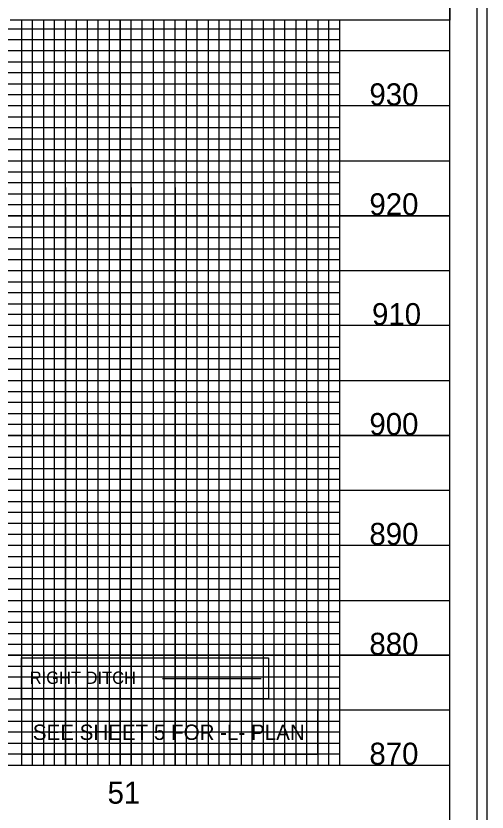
# Model space of a CAD drawing. Extents: x 1648649 to 1651827, y 844691 to 845879.
# Drawn here: x 1651431.8 to 1651646.3, y 845244.7 to 845606.9 of the extents above; entities that cross this region are included whole.
import ezdxf

# ---------------------------------------------------------------- set-up
doc = ezdxf.new("R2010")
doc.units = 0
for name, color, linetype in [('Exist Vertical Profile Horizontal Axis Label Major', 7, 'Continuous'), ('Exist Vertical Profile Vertical Axis Label', 7, 'Continuous'), ('Prop Dimension', 7, 'Continuous'), ('Prop Grid Mask', 7, 'Continuous'), ('Prop PFL Ditch Label CELL', 7, 'Continuous'), ('Sheet DOT Grid CELL', 7, 'Continuous'), ('Sheet Plot Border Inside CELL', 7, 'Continuous'), ('Sheet Plot Border Outside CELL', 7, 'Continuous'), ('Sheet Profile CELL', 7, 'Continuous'), ('Sheet Profile Grid Major CELL', 7, 'Continuous'), ('Sheet Profile Grid Middle CELL', 7, 'Continuous'), ('Sheet Profile Grid Minor CELL', 7, 'Continuous'), ('Sheet Sticker Exception Certification CELL', 7, 'Continuous')]:
    doc.layers.add(name, color=color, linetype=linetype)

msp = doc.modelspace()

# ---------------------------------------------------------------- linework, layer by layer
at = {"layer": 'Prop Grid Mask'}
for points in [[(1651434.32, 845314.94), (1651546.82, 845314.94), (1651546.82, 845296.19), (1651434.32, 845296.19)], [(1651434.32, 845314.94), (1651546.82, 845314.94), (1651546.82, 845296.19), (1651434.32, 845296.19)], [(1651434.28, 845291.02), (1651434.28, 845271.02), (1651569.28, 845271.02), (1651569.28, 845291.02)]]:
    msp.add_lwpolyline(points, close=True, dxfattribs=at)
at = {"layer": 'Prop PFL Ditch Label CELL'}
for p, q in [((1651434.32, 845303.69), (1651434.32, 845303.69)), ((1651498.49, 845305.46), (1651543.49, 845305.46))]:
    msp.add_line(p, q, dxfattribs=at)
at = {"layer": 'Sheet DOT Grid CELL'}
for p, q in [((1651479.28, 845266.02), (1651479.28, 845604.97)), ((1651479.28, 845266.02), (1651479.28, 845604.97)), ((1651529.28, 845266.02), (1651529.28, 845604.97)), ((1651529.28, 845266.02), (1651529.28, 845604.97)), ((1651579.28, 845266.02), (1651579.28, 845604.97)), ((1651579.28, 845266.02), (1651579.28, 845604.97)), ((1651629.28, 845566.02), (1650129.28, 845566.02)), ((1651629.28, 845566.02), (1650129.28, 845566.02)), ((1651629.28, 845516.02), (1650129.28, 845516.02)), ((1651629.28, 845516.02), (1650129.28, 845516.02)), ((1651629.28, 845466.02), (1650129.28, 845466.02)), ((1651629.28, 845466.02), (1650129.28, 845466.02)), ((1651629.28, 845416.02), (1650129.28, 845416.02)), ((1651629.28, 845416.02), (1650129.28, 845416.02)), ((1651629.28, 845366.02), (1650129.28, 845366.02)), ((1651629.28, 845366.02), (1650129.28, 845366.02)), ((1651629.28, 845316.02), (1650129.28, 845316.02)), ((1651629.28, 845316.02), (1650129.28, 845316.02))]:
    msp.add_line(p, q, dxfattribs=at)
at = {"layer": 'Sheet Plot Border Inside CELL'}
msp.add_lwpolyline([(1649975.28, 844713.47), (1651641.78, 844713.47), (1651641.78, 845768.57), (1649975.28, 845768.57)], close=True, dxfattribs=at)
at = {"layer": 'Sheet Plot Border Outside CELL'}
msp.add_lwpolyline([(1649962.28, 844691.02), (1651646.28, 844691.02), (1651646.28, 845791.02), (1649962.28, 845791.02)], close=True, dxfattribs=at)
at = {"layer": 'Sheet Profile CELL'}
msp.add_line((1650129.28, 845266.02), (1651629.28, 845266.02), dxfattribs=at)
msp.add_lwpolyline([(1651629.28, 845766.02), (1650129.28, 845766.02), (1650129.28, 844716.02), (1651629.28, 844716.02)], close=True, dxfattribs=at)
at = {"layer": 'Sheet Profile Grid Major CELL'}
for points in [[(1651479.28, 845604.97), (1651479.28, 845266.02), (1651529.28, 845266.02), (1651529.28, 845266.02), (1651529.28, 845604.97)], [(1651579.28, 845266.02), (1651579.28, 845604.97)], [(1651629.28, 845566.02), (1650129.28, 845566.02), (1650129.28, 845516.02), (1651629.28, 845516.02)], [(1651629.28, 845466.02), (1650129.28, 845466.02), (1650129.28, 845416.02), (1651629.28, 845416.02)], [(1651629.28, 845366.02), (1650129.28, 845366.02), (1650129.28, 845366.02), (1650129.28, 845316.02), (1651629.28, 845316.02)]]:
    msp.add_lwpolyline(points, dxfattribs=at)
at = {"layer": 'Sheet Profile Grid Middle CELL'}
for points in [[(1651404.28, 845738.96), (1651404.28, 845266.02), (1651454.28, 845266.02), (1651454.28, 845604.97)], [(1651454.28, 845528.82), (1651454.28, 845266.02), (1651504.28, 845266.02), (1651504.28, 845604.97)], [(1651504.28, 845528.82), (1651504.28, 845266.02), (1651554.28, 845266.02), (1651554.28, 845604.97)], [(1651629.28, 845591.02), (1650129.28, 845591.02), (1650129.28, 845541.02), (1651454.28, 845541.02)], [(1651454.28, 845541.02), (1651629.28, 845541.02)], [(1651454.28, 845541.02), (1651629.28, 845541.02)], [(1651629.28, 845491.02), (1650129.28, 845491.02), (1650129.28, 845441.02), (1651629.28, 845441.02)], [(1651629.28, 845391.02), (1650129.28, 845391.02), (1650129.28, 845341.02), (1651629.28, 845341.02)], [(1651629.28, 845291.02), (1650129.28, 845291.02)]]:
    msp.add_lwpolyline(points, dxfattribs=at)
at = {"layer": 'Sheet Profile Grid Minor CELL'}
for p, q in [((1650179.28, 845601.02), (1651579.28, 845601.02)), ((1651579.28, 845581.02), (1650179.28, 845581.02)), ((1650179.28, 845576.02), (1651579.28, 845576.02)), ((1651579.28, 845556.02), (1650179.28, 845556.02)), ((1650179.28, 845551.02), (1651579.28, 845551.02)), ((1651579.28, 845531.02), (1650179.28, 845531.02)), ((1650179.28, 845526.02), (1651579.28, 845526.02)), ((1651579.28, 845521.02), (1650179.28, 845521.02)), ((1650179.28, 845511.02), (1651579.28, 845511.02)), ((1651579.28, 845506.02), (1650179.28, 845506.02)), ((1650179.28, 845501.02), (1651579.28, 845501.02)), ((1651579.28, 845496.02), (1650179.28, 845496.02)), ((1650179.28, 845486.02), (1651579.28, 845486.02)), ((1651579.28, 845481.02), (1650179.28, 845481.02)), ((1650179.28, 845476.02), (1651579.28, 845476.02)), ((1651579.28, 845471.02), (1650179.28, 845471.02)), ((1650179.28, 845461.02), (1651579.28, 845461.02)), ((1651579.28, 845456.02), (1650179.28, 845456.02)), ((1650179.28, 845451.02), (1651579.28, 845451.02)), ((1651579.28, 845446.02), (1650179.28, 845446.02)), ((1650179.28, 845436.02), (1651579.28, 845436.02)), ((1651579.28, 845431.02), (1650179.28, 845431.02)), ((1650179.28, 845426.02), (1651579.28, 845426.02)), ((1651579.28, 845421.02), (1650179.28, 845421.02)), ((1650179.28, 845411.02), (1651579.28, 845411.02)), ((1651579.28, 845406.02), (1650179.28, 845406.02)), ((1650179.28, 845401.02), (1651579.28, 845401.02)), ((1651579.28, 845396.02), (1650179.28, 845396.02)), ((1650179.28, 845386.02), (1651579.28, 845386.02)), ((1651579.28, 845381.02), (1650179.28, 845381.02)), ((1651579.28, 845376.02), (1650179.28, 845376.02)), ((1651579.28, 845371.02), (1650179.28, 845371.02)), ((1650179.28, 845361.02), (1651579.28, 845361.02)), ((1651579.28, 845356.02), (1650179.28, 845356.02)), ((1650179.28, 845351.02), (1651579.28, 845351.02)), ((1651579.28, 845346.02), (1650179.28, 845346.02)), ((1650179.28, 845336.02), (1651579.28, 845336.02)), ((1651579.28, 845331.02), (1650179.28, 845331.02)), ((1650179.28, 845326.02), (1651579.28, 845326.02)), ((1651579.28, 845321.02), (1650179.28, 845321.02)), ((1650179.28, 845311.02), (1651579.28, 845311.02)), ((1651579.28, 845306.02), (1650179.28, 845306.02)), ((1650179.28, 845301.02), (1651579.28, 845301.02)), ((1651579.28, 845296.02), (1650179.28, 845296.02)), ((1650179.28, 845286.02), (1651579.28, 845286.02)), ((1651579.28, 845281.02), (1650179.28, 845281.02)), ((1650179.28, 845276.02), (1651579.28, 845276.02))]:
    msp.add_line(p, q, dxfattribs=at)
for points in [[(1651434.28, 845604.97), (1651434.28, 845266.02), (1651439.28, 845266.02), (1651439.28, 845604.97)], [(1651444.28, 845604.97), (1651444.28, 845266.02), (1651449.28, 845266.02), (1651449.28, 845604.97)], [(1651459.28, 845604.97), (1651459.28, 845266.02), (1651459.28, 845266.02), (1651464.28, 845266.02), (1651469.28, 845266.02), (1651469.28, 845604.97)], [(1651464.28, 845604.97), (1651464.28, 845266.02)], [(1651474.28, 845604.97), (1651474.18, 845266.07), (1651479.18, 845266.07), (1651484.28, 845266.02), (1651484.28, 845604.97)], [(1651484.28, 845528.82), (1651484.28, 845266.02), (1651489.28, 845266.02), (1651489.28, 845604.97)], [(1651494.28, 845604.97), (1651494.28, 845266.02), (1651499.28, 845266.02), (1651499.28, 845604.97)], [(1651509.28, 845604.97), (1651509.28, 845266.02), (1651514.28, 845266.02), (1651514.28, 845604.97)], [(1651519.28, 845604.97), (1651519.28, 845266.02), (1651524.28, 845266.02), (1651524.28, 845604.97)], [(1651534.28, 845604.97), (1651534.28, 845266.02), (1651539.28, 845266.02), (1651539.28, 845604.97)], [(1651544.28, 845604.97), (1651544.28, 845266.02), (1651549.28, 845266.02), (1651549.28, 845604.97)], [(1651559.28, 845604.97), (1651559.28, 845266.02), (1651564.28, 845266.02), (1651564.28, 845604.97)], [(1651569.28, 845604.97), (1651569.28, 845266.02), (1651574.28, 845266.02), (1651574.28, 845604.97)], [(1651579.28, 845596.02), (1650179.28, 845596.02), (1650179.28, 845586.02), (1651579.28, 845586.02)], [(1651579.28, 845571.02), (1650179.28, 845571.02), (1650179.28, 845561.02), (1651579.28, 845561.02)], [(1651579.28, 845546.02), (1650179.28, 845546.02), (1650179.28, 845536.02), (1651579.28, 845536.02)], [(1651579.28, 845271.02), (1650179.28, 845271.02)]]:
    msp.add_lwpolyline(points, dxfattribs=at)
at = {"layer": 'Sheet Sticker Exception Certification CELL'}
for p, q in [((1651629.27, 845628.46), (1651629.27, 845604.96)), ((1651629.27, 845628.46), (1651629.27, 845604.96)), ((1651629.27, 845604.97), (1651429.23, 845604.97)), ((1651629.27, 845604.97), (1651429.23, 845604.97))]:
    msp.add_line(p, q, dxfattribs=at)

# ---------------------------------------------------------------- texts
at = {"layer": 'Exist Vertical Profile Horizontal Axis Label Major'}
msp.add_text('51', height=10, dxfattribs=at).set_placement((1651473.51, 845248.52))
at = {"layer": 'Exist Vertical Profile Vertical Axis Label'}
for s, p in [('930', (1651592.71, 845566.27)), ('920', (1651592.71, 845516.27)), ('910', (1651593.91, 845466.27)), ('900', (1651592.71, 845416.27)), ('890', (1651592.71, 845366.27)), ('880', (1651592.71, 845316.27)), ('870', (1651592.71, 845266.27))]:
    msp.add_text(s, height=10, dxfattribs=at).set_placement(p)
at = {"layer": 'Prop Dimension'}
msp.add_text('SEE SHEET 5 FOR -L- PLAN', height=7, dxfattribs=at).set_placement((1651439.47, 845277.52))
at = {"layer": 'Prop PFL Ditch Label CELL'}
msp.add_text('RIGHT DITCH', height=5.6137, dxfattribs=at).set_placement((1651438.07, 845303.02))

doc.saveas('drawing.dxf')
